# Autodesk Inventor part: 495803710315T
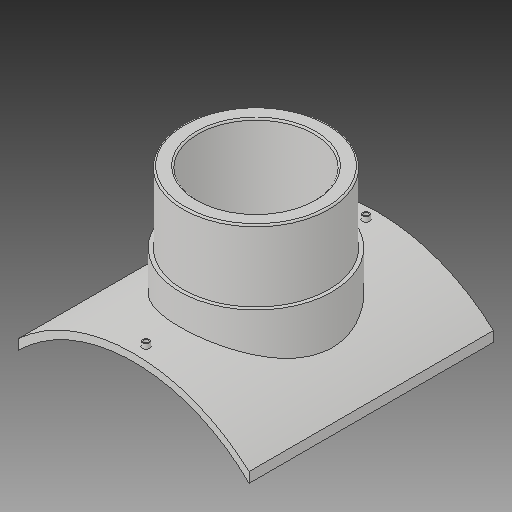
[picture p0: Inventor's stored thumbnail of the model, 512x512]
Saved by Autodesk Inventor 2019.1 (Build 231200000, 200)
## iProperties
Created: 2017-10
Part Number: 495803710315T
Material: Generic
Description: PLASSON BRANCH SADDLE  710x315
Document SubType Name: Modeling
Designer: KIM
Mass: 2754.05 g
Surface Area: 3037.44 cm^2
Volume: 2754.05 cm^3
Density: 1 g/cm^3
Appearance: Default
Author: KIM
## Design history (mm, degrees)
derived "495803.ipt"
feature "Solid1::495803.ipt"
tag "TaggingFeature1"
body "Solid1"
other parameters: "d1" = 16, "d4" = 0, "d12" = 380.6, "d13" = 14, "d14" = 238.5, "d16" = 5 deg, "d18" = 4, "d19" = 14, "d20" = 0, "d21" = 3, "d22" = 0, "d23" = 591, "d24" = 330.75, "d25" = 16, "d26" = 252, "d28" = 0, "d29" = 9.6, "d31" = 0, "d33" = 0, "d34" = 7.1, "d36" = 315, "d37" = 154, "d38" = 0, "d39" = 3.55, "d_1" = 315, "x_" = 16, "D_" = 16
